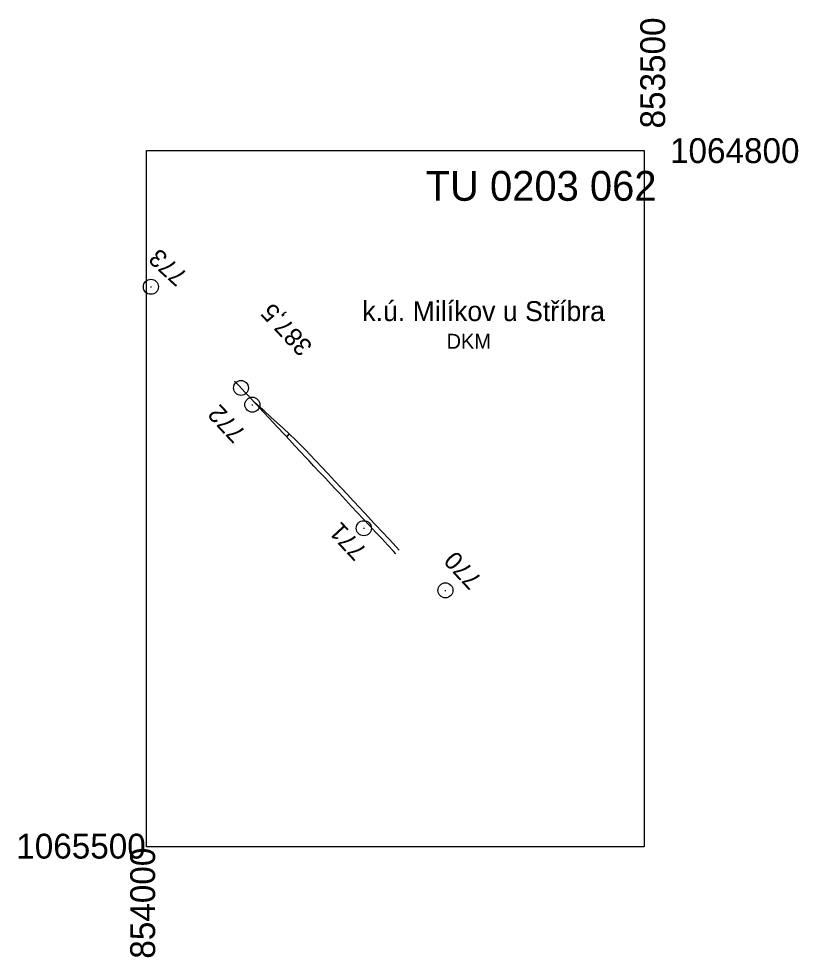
# Model space of a CAD drawing. Extents: x -867628 to -843257, y -1065611 to -1039859.
# Drawn here: x -854128 to -853345, y -1065611 to -1064667 of the extents above; entities that cross this region are included whole.
import ezdxf

# ---------------------------------------------------------------- set-up
doc = ezdxf.new("R2010")
doc.units = 0
for name, color, linetype in [('Vrstva 1', 7, 'Continuous'), ('Vrstva 10', 7, 'Continuous'), ('Vrstva 55', 7, 'Continuous'), ('Vrstva 62', 7, 'Continuous'), ('Vrstva 63', 7, 'Continuous'), ('Vrstva 7', 7, 'Continuous')]:
    doc.layers.add(name, color=color, linetype=linetype)

msp = doc.modelspace()

# ---------------------------------------------------------------- linework, layer by layer
at = {"layer": 'Vrstva 1'}
for points in [[(-853905.66, -1065037.87), (-853906.89, -1065036.56), (-853911.51, -1065031.61)], [(-853876.48, -1065069.16), (-853882.72, -1065062.46), (-853889.08, -1065055.64), (-853891.46, -1065053.1), (-853894.18, -1065050.19), (-853905.11, -1065038.46), (-853905.66, -1065037.87)], [(-853875.16, -1065067.89), (-853881.94, -1065061.65), (-853883.24, -1065060.43), (-853891.46, -1065053.1), (-853894.18, -1065050.19), (-853905.11, -1065038.46), (-853905.66, -1065037.87)], [(-853749.58, -1065205.18), (-853751.8, -1065202.8), (-853757.51, -1065196.66), (-853763.66, -1065190.07), (-853769.78, -1065183.5), (-853775.92, -1065176.92), (-853782.06, -1065170.34), (-853788.2, -1065163.77), (-853793.91, -1065157.64), (-853800.05, -1065151.06), (-853806.2, -1065144.48), (-853810.51, -1065139.86), (-853814.4, -1065135.69), (-853820.29, -1065129.38), (-853826.11, -1065123.16), (-853831.81, -1065117.04), (-853836.61, -1065111.89), (-853839.56, -1065108.73), (-853845.2, -1065102.69), (-853850.88, -1065096.6), (-853856.35, -1065090.74), (-853862.06, -1065084.61), (-853867.93, -1065078.32), (-853873.28, -1065072.59), (-853876.48, -1065069.16)], [(-853764.16, -1065182.22), (-853768.52, -1065177.55), (-853771.46, -1065174.39), (-853777.06, -1065168.39), (-853780.95, -1065164.21), (-853785.95, -1065158.85), (-853792.08, -1065152.28), (-853798.43, -1065145.47), (-853804.35, -1065139.12), (-853810.67, -1065132.35), (-853814.37, -1065128.4), (-853817.88, -1065124.63), (-853823.82, -1065118.27), (-853829.91, -1065111.73), (-853835.93, -1065105.32), (-853839.73, -1065101.37), (-853843.7, -1065097.34), (-853849.98, -1065091.13), (-853856.48, -1065084.93), (-853862.48, -1065079.4), (-853868.89, -1065073.57), (-853875.16, -1065067.89)], [(-853746.03, -1065201.65), (-853749.1, -1065198.36), (-853756.01, -1065190.96), (-853764.16, -1065182.22)]]:
    msp.add_lwpolyline(points, dxfattribs=at)
at = {"layer": 'Vrstva 62'}
msp.add_lwpolyline([(-853500, -1064800), (-853500, -1065500), (-854000, -1065500), (-854000, -1064800)], close=True, dxfattribs=at)
at = {"layer": 'Vrstva 63'}
for p, q in [((-853996.08, -1064936.9), (-853995.08, -1064936.9)), ((-853894.18, -1065055.39), (-853893.18, -1065055.39)), ((-853782.14, -1065179.56), (-853781.14, -1065179.56)), ((-853700.15, -1065242.02), (-853699.15, -1065242.02))]:
    msp.add_line(p, q, dxfattribs=at)
for centre in [(-853995.58, -1064936.9), (-853893.68, -1065055.39), (-853781.64, -1065179.56), (-853699.65, -1065242.02)]:
    msp.add_circle(centre, 7.56, dxfattribs=at)
at = {"layer": 'Vrstva 7'}
for p, q in [((-853859.48, -1065087.38), (-853856.81, -1065084.72)), ((-853859.07, -1065087.82), (-853856.38, -1065085.13)), ((-853857.88, -1065086.2), (-853857.88, -1065086.2))]:
    msp.add_line(p, q, dxfattribs=at)
msp.add_circle((-853905.08, -1065038.5), 7.5, dxfattribs=at)

# ---------------------------------------------------------------- texts
at = {"layer": 'Vrstva 10'}
msp.add_text('DKM', height=15, dxfattribs=at).set_placement((-853698.5, -1064999.15))
at = {"layer": 'Vrstva 55'}
msp.add_text('k.ú. Milíkov u Stříbra', height=20, dxfattribs=at).set_placement((-853783.13, -1064971.34))
at = {"layer": 'Vrstva 62'}
for s, p in [('853500', (-853478.89, -1064777.72)), ('854000', (-853991.39, -1065612.26))]:
    msp.add_text(s, height=25, rotation=90, dxfattribs=at).set_placement(p)
for s, height, p in [('1064800', 25, (-853474.02, -1064812.53)), ('TU 0203 062', 30, (-853719.5, -1064850.43)), ('1065500', 25, (-854130.9, -1065511.65))]:
    msp.add_text(s, height=height, dxfattribs=at).set_placement(p)
at = {"layer": 'Vrstva 63'}
for s, rotation, p in [('773', 137.83515, (-853957.61, -1064924.32)), ('772', 133.06437, (-853899.2, -1065083.16)), ('771', 133.04335, (-853777.37, -1065201.5)), ('770', 133.04381, (-853661.95, -1065230.55))]:
    msp.add_text(s, height=18, rotation=rotation, dxfattribs=at).set_placement(p)
at = {"layer": 'Vrstva 7'}
msp.add_text('387,5', height=18, rotation=133.01282, dxfattribs=at).set_placement((-853832.29, -1064996.02))

doc.saveas('drawing.dxf')
